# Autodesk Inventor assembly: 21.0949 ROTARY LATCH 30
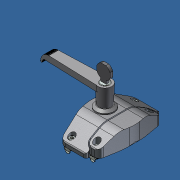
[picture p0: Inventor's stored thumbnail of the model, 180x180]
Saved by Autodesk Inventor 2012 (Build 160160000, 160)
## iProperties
Created: 2014-06
Part Number: 21.0949 ROTARY LATCH 30
Document SubType Name: Assembly
Designer: Admin
Mass: 450 g
Surface Area: 544.981 cm^2
Volume: 138.831 cm^3
Author: Admin
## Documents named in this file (3)
- C:\Andys Backup Data\ANDY'S INVENTOR\INVENTOR LIBRARIES\PARTS LIBRARY\30 SERIES\21.0949 ROTARY LATCH 30.iam
- C:\Andys Backup Data\ANDY'S INVENTOR\INVENTOR LIBRARIES\PARTS LIBRARY\30 SERIES\SUBCOMPONENTS\21.0949 ROTARY LATCH 30 HANDLE SIDE.ipt
- C:\Andys Backup Data\ANDY'S INVENTOR\INVENTOR LIBRARIES\PARTS LIBRARY\30 SERIES\SUBCOMPONENTS\21.0949 ROTARY LATCH 30 CATCH SIDE.ipt
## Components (2 placed, 2 different names)
1. 21.0949 ROTARY LATCH 30 HANDLE SIDE:1 — Flush:1, Flush:2, Mate:1
2. 21.0949 ROTARY LATCH 30 CATCH SIDE:1 — Flush:1, Flush:2, Mate:1
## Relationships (3: Flush 2, Mate 1)
- Flush:1: 21.0949 ROTARY LATCH 30 HANDLE SIDE:1 ↔ 21.0949 ROTARY LATCH 30 CATCH SIDE:1
- Flush:2: 21.0949 ROTARY LATCH 30 HANDLE SIDE:1 ↔ 21.0949 ROTARY LATCH 30 CATCH SIDE:1
- Mate:1: 21.0949 ROTARY LATCH 30 HANDLE SIDE:1 ↔ 21.0949 ROTARY LATCH 30 CATCH SIDE:1
